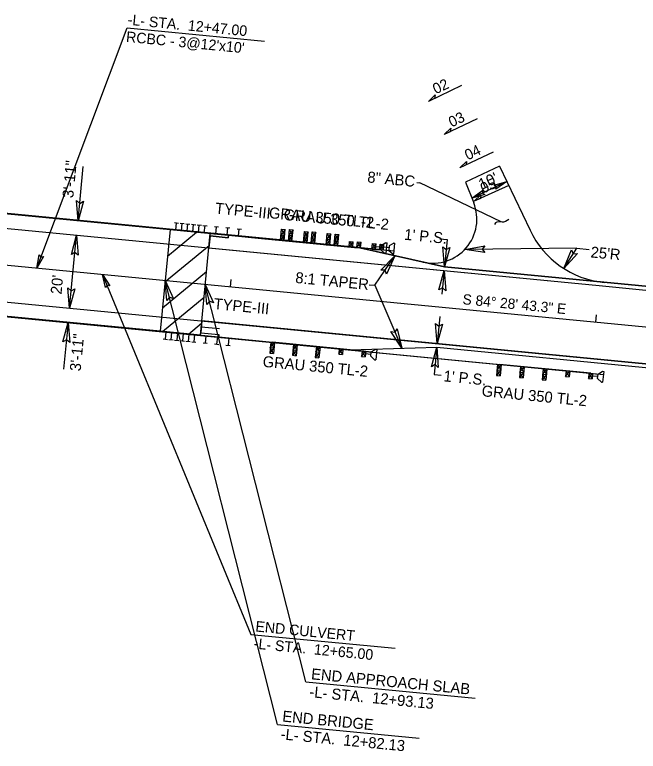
# Model space of a CAD drawing. Extents: x 2061030 to 2061632, y 912568 to 912882.
# Drawn here: x 2061270.2 to 2061440.1, y 912568.1 to 912768.6 of the extents above; entities that cross this region are included whole.
import ezdxf

# ---------------------------------------------------------------- set-up
doc = ezdxf.new("R2010")
doc.units = 0
for name, color, linetype in [('Prop Approach Slab', 7, 'Continuous'), ('Prop Approach Slab Hatching', 7, 'Continuous'), ('Prop Conc Shoulder Berm Gutter', 7, 'Continuous'), ('Prop Dimension', 7, 'Continuous'), ('Prop Dimension Text', 7, 'Continuous'), ('Prop EOT', 7, 'Continuous'), ('Prop Guardrail', 7, 'Continuous'), ('Prop Guardrail Anchor Unit CELL', 7, 'Continuous'), ('Prop Horizontal Alignment', 7, 'Continuous'), ('Prop Horizontal Alignment Direction Label', 7, 'Continuous'), ('Prop Horizontal Alignment Station Label', 7, 'Continuous'), ('Prop Horizontal Alignment Tick Small', 7, 'Continuous'), ('Prop Paved Shoulder', 7, 'Continuous'), ('Prop Roadway Bridge', 7, 'Continuous'), ('Prop Shade Medium', 7, 'Continuous'), ('Prop Structure Anchor Unit CELL', 7, 'Continuous'), ('Prop Terminator CELL', 7, 'Continuous'), ('Scratch_Level_0', 7, 'Continuous')]:
    doc.layers.add(name, color=color, linetype=linetype)

msp = doc.modelspace()

# ---------------------------------------------------------------- linework, layer by layer
at = {"layer": 'Prop Approach Slab'}
for p, q in [((2061323.44, 912709.06), (2061312.49, 912710.12)), ((2061320.76, 912681.36), (2061323.44, 912709.06)), ((2061309.81, 912682.42), (2061320.76, 912681.36))]:
    msp.add_line(p, q, dxfattribs=at)
at = {"layer": 'Prop Approach Slab Hatching'}
for p, q in [((2061311.8, 912702.92), (2061319.7, 912709.43)), ((2061311.11, 912695.88), (2061323.12, 912705.77)), ((2061310.43, 912688.84), (2061322.44, 912698.73)), ((2061310.43, 912682.36), (2061321.76, 912691.69)), ((2061317.47, 912681.68), (2061321.08, 912684.66))]:
    msp.add_line(p, q, dxfattribs=at)
at = {"layer": 'Prop Conc Shoulder Berm Gutter'}
for p, q in [((2061323.44, 912709.06), (2061328.42, 912708.58)), ((2061320.99, 912683.68), (2061325.96, 912683.2)), ((2061320.76, 912681.36), (2061325.74, 912680.88))]:
    msp.add_line(p, q, dxfattribs=at)
at = {"layer": 'Prop Dimension'}
for p, q in [((2061287.41, 912712.55), (2061288.84, 912727.3)), ((2061404.29, 912723.22), (2061394.74, 912718.7)), ((2061379.7, 912722.94), (2061380.52, 912722.86)), ((2061402.72, 912712.22), (2061380.52, 912722.86)), ((2061285.11, 912688.74), (2061287.03, 912708.65)), ((2061385.96, 912707.6), (2061387.99, 912707.4)), ((2061387.99, 912707.4), (2061387.27, 912699.96)), ((2061423.3, 912705.04), (2061392.81, 912704.73)), ((2061419.8, 912699.52), (2061423.3, 912705.04)), ((2061423.3, 912705.04), (2061426.67, 912704.71)), ((2061368.25, 912694.97), (2061373.73, 912703)), ((2061387.17, 912698.97), (2061386.55, 912692.53)), ((2061366.76, 912695.11), (2061368.25, 912694.97)), ((2061368.25, 912694.97), (2061375.66, 912677.8)), ((2061284.73, 912684.84), (2061283.5, 912672.13)), ((2061385.97, 912686.5), (2061385.25, 912679.06)), ((2061385.15, 912678.07), (2061384.43, 912670.63)), ((2061384.43, 912670.63), (2061386.34, 912670.45))]:
    msp.add_line(p, q, dxfattribs=at)
for points in [[(2061398.22, 912703.85), (2061392.81, 912704.73), (2061398.23, 912705.74), (2061397.55, 912704.78)], [(2061423.48, 912703.59), (2061419.8, 912699.52), (2061421.9, 912704.62), (2061422.34, 912703.53)]]:
    msp.add_lwpolyline(points, close=True, dxfattribs=at)
msp.add_open_spline([(2061404.75, 912712.9), (2061403.43, 912711.84), (2061402.8, 912712.5), (2061401.08, 912712.16), (2061400.88, 912711.53)], degree=3, dxfattribs=at)
at = {"layer": 'Prop EOT'}
for p, q in [((2061105.95, 912726.15), (2061429.44, 912694.88)), ((2061104.02, 912706.25), (2061477.28, 912670.17)), ((2061429.44, 912694.88), (2061479.21, 912690.07))]:
    msp.add_line(p, q, dxfattribs=at)
at = {"layer": 'Prop Guardrail'}
for p, q in [((2061343.1, 912707.16), (2061331.15, 912708.32)), ((2061328.48, 912680.62), (2061340.42, 912679.46))]:
    msp.add_line(p, q, dxfattribs=at)
at = {"layer": 'Prop Guardrail Anchor Unit CELL'}
for p, q in [((2061342.6, 912707.21), (2061342.89, 912710.23)), ((2061343.89, 912710.14), (2061342.75, 912708.72)), ((2061343.74, 912708.63), (2061342.89, 912710.23)), ((2061342.89, 912710.23), (2061343.89, 912710.14)), ((2061343.6, 912707.12), (2061343.89, 912710.14)), ((2061348.82, 912706.61), (2061349.11, 912709.63)), ((2061350.11, 912709.54), (2061348.97, 912708.12)), ((2061349.96, 912708.03), (2061349.11, 912709.63)), ((2061349.11, 912709.63), (2061350.11, 912709.54)), ((2061349.82, 912706.52), (2061350.11, 912709.54)), ((2061355.04, 912706.01), (2061355.33, 912709.03)), ((2061356.33, 912708.94), (2061355.19, 912707.52)), ((2061356.19, 912707.43), (2061355.33, 912709.03)), ((2061355.33, 912709.03), (2061356.33, 912708.94)), ((2061356.04, 912705.91), (2061356.33, 912708.94)), ((2061342.6, 912707.21), (2061343.74, 912708.63)), ((2061342.6, 912707.21), (2061343.6, 912707.12)), ((2061342.75, 912708.72), (2061343.74, 912708.63)), ((2061342.75, 912708.72), (2061343.6, 912707.12)), ((2061367.98, 912704.76), (2061343.1, 912707.16)), ((2061348.82, 912706.61), (2061349.96, 912708.03)), ((2061348.97, 912708.12), (2061349.96, 912708.03)), ((2061348.97, 912708.12), (2061349.82, 912706.52)), ((2061355.04, 912706.01), (2061356.19, 912707.43)), ((2061355.19, 912707.52), (2061356.19, 912707.43)), ((2061355.19, 912707.52), (2061356.04, 912705.91)), ((2061361.26, 912705.41), (2061361.41, 912706.92)), ((2061361.41, 912706.92), (2061362.41, 912706.82)), ((2061361.41, 912706.92), (2061362.26, 912705.31)), ((2061348.82, 912706.61), (2061349.82, 912706.52)), ((2061355.04, 912706.01), (2061356.04, 912705.91)), ((2061361.26, 912705.41), (2061362.41, 912706.82)), ((2061361.26, 912705.41), (2061362.26, 912705.31)), ((2061362.26, 912705.31), (2061362.41, 912706.82)), ((2061367.48, 912704.81), (2061367.63, 912706.32)), ((2061367.48, 912704.81), (2061368.63, 912706.22)), ((2061367.63, 912706.32), (2061368.63, 912706.22)), ((2061367.63, 912706.32), (2061368.48, 912704.71)), ((2061368.48, 912704.71), (2061368.63, 912706.22)), ((2061370.01, 912705.3), (2061368.55, 912705.44)), ((2061370.06, 912705.8), (2061369.94, 912704.58)), ((2061371.31, 912706.54), (2061370.06, 912705.8)), ((2061371.31, 912706.54), (2061371.62, 912706.51)), ((2061371.34, 912703.59), (2061371.62, 912706.51)), ((2061367.48, 912704.81), (2061368.48, 912704.71)), ((2061368.48, 912704.72), (2061369.95, 912704.58)), ((2061369.95, 912704.58), (2061371.04, 912703.61)), ((2061371.04, 912703.61), (2061371.34, 912703.59)), ((2061339.92, 912679.51), (2061339.63, 912676.49)), ((2061339.78, 912678), (2061340.92, 912679.41)), ((2061339.92, 912679.51), (2061340.92, 912679.41)), ((2061339.92, 912679.51), (2061340.77, 912677.9)), ((2061365.3, 912677.06), (2061340.42, 912679.46)), ((2061340.92, 912679.41), (2061340.63, 912676.39)), ((2061346.14, 912678.91), (2061345.85, 912675.89)), ((2061346.14, 912678.91), (2061347.14, 912678.81)), ((2061346.14, 912678.91), (2061346.99, 912677.3)), ((2061340.77, 912677.9), (2061339.63, 912676.49)), ((2061339.78, 912678), (2061340.77, 912677.9)), ((2061340.63, 912676.39), (2061339.78, 912678)), ((2061346.99, 912677.3), (2061345.85, 912675.89)), ((2061346, 912677.4), (2061347.14, 912678.81)), ((2061346, 912677.4), (2061346.99, 912677.3)), ((2061346.85, 912675.79), (2061346, 912677.4)), ((2061347.14, 912678.81), (2061346.85, 912675.79)), ((2061352.37, 912678.31), (2061352.07, 912675.28)), ((2061352.22, 912676.79), (2061353.36, 912678.21)), ((2061352.37, 912678.31), (2061353.36, 912678.21)), ((2061352.37, 912678.31), (2061353.21, 912676.7)), ((2061353.36, 912678.21), (2061353.07, 912675.19)), ((2061358.59, 912677.7), (2061358.44, 912676.19)), ((2061358.44, 912676.19), (2061359.58, 912677.61)), ((2061358.59, 912677.7), (2061359.58, 912677.61)), ((2061358.59, 912677.7), (2061359.44, 912676.1)), ((2061359.58, 912677.61), (2061359.44, 912676.1)), ((2061364.81, 912677.1), (2061364.66, 912675.59)), ((2061364.66, 912675.59), (2061365.8, 912677.01)), ((2061364.81, 912677.1), (2061365.8, 912677.01)), ((2061364.81, 912677.1), (2061365.66, 912675.5)), ((2061365.8, 912677.01), (2061365.66, 912675.5)), ((2061365.8, 912677), (2061367.27, 912676.85)), ((2061367.15, 912675.63), (2061367.26, 912676.85)), ((2061367.27, 912676.85), (2061368.52, 912677.59)), ((2061368.52, 912677.59), (2061368.83, 912677.56)), ((2061368.83, 912677.56), (2061368.54, 912674.64)), ((2061339.63, 912676.49), (2061340.63, 912676.39)), ((2061345.85, 912675.89), (2061346.85, 912675.79)), ((2061353.21, 912676.7), (2061352.07, 912675.28)), ((2061352.07, 912675.28), (2061353.07, 912675.19)), ((2061352.22, 912676.79), (2061353.21, 912676.7)), ((2061353.07, 912675.19), (2061352.22, 912676.79)), ((2061358.44, 912676.19), (2061359.44, 912676.1)), ((2061364.66, 912675.59), (2061365.66, 912675.5)), ((2061367.19, 912676.14), (2061365.73, 912676.28)), ((2061368.23, 912674.67), (2061367.15, 912675.63)), ((2061368.23, 912674.67), (2061368.54, 912674.64))]:
    msp.add_line(p, q, dxfattribs=at)
at = {"layer": 'Prop Horizontal Alignment'}
msp.add_line((2061030.33, 912723.42), (2061621.2, 912666.3), dxfattribs=at)
at = {"layer": 'Prop Horizontal Alignment Station Label'}
for p, q in [((2061341.76, 912575.36), (2061311.15, 912696.27)), ((2061349.5, 912586.98), (2061322.1, 912695.21)), ((2061349.5, 912586.98), (2061395.65, 912582.52)), ((2061341.76, 912575.36), (2061380.35, 912571.63))]:
    msp.add_line(p, q, dxfattribs=at)
at = {"layer": 'Prop Horizontal Alignment Tick Small'}
for p, q in [((2061328.94, 912694.55), (2061329.13, 912696.54)), ((2061428.48, 912684.93), (2061428.67, 912686.92))]:
    msp.add_line(p, q, dxfattribs=at)
at = {"layer": 'Prop Paved Shoulder'}
for p, q in [((2061402.29, 912727.44), (2061393.02, 912723.05)), ((2061402.29, 912727.44), (2061410.58, 912709.94)), ((2061393.02, 912723.05), (2061395.26, 912717.37)), ((2061323.44, 912709.06), (2061312.49, 912710.12)), ((2061387.27, 912699.96), (2061479.3, 912691.07)), ((2061320.76, 912681.36), (2061309.81, 912682.42)), ((2061385.15, 912678.07), (2061477.19, 912669.17))]:
    msp.add_line(p, q, dxfattribs=at)
for points in [[(2061323.38, 912708.4), (2061328.35, 912707.92), (2061328.42, 912708.58), (2061337.38, 912707.72), (2061362.76, 912705.26), (2061364.22, 912705.14), (2061387.27, 912699.96)], [(2061320.83, 912682.02), (2061325.8, 912681.54), (2061325.74, 912680.88), (2061334.7, 912680.01), (2061360.08, 912677.56), (2061361.54, 912677.41), (2061385.15, 912678.07)]]:
    msp.add_lwpolyline(points, dxfattribs=at)
for centre, radius, start, end in [((2061384.09, 912712.98), 12, 257.3546, 21.4729), ((2061433.17, 912720.64), 25, 205.3407, 264.4787)]:
    msp.add_arc(centre, radius, start, end, dxfattribs=at)
at = {"layer": 'Prop Roadway Bridge'}
for p, q in [((2061240.58, 912717.07), (2061312.49, 912710.12)), ((2061312.49, 912710.12), (2061309.81, 912682.42)), ((2061309.81, 912682.42), (2061237.9, 912689.37))]:
    msp.add_line(p, q, dxfattribs=at)
at = {"layer": 'Prop Shade Medium'}
for p, q in [((2061323.38, 912708.4), (2061323.06, 912705.17)), ((2061323.06, 912705.17), (2061429.44, 912694.88)), ((2061479.3, 912691.07), (2061387.27, 912699.96)), ((2061429.44, 912694.88), (2061479.21, 912690.07)), ((2061321.14, 912685.26), (2061320.83, 912682.02)), ((2061477.28, 912670.17), (2061321.14, 912685.26)), ((2061385.15, 912678.07), (2061477.19, 912669.17))]:
    msp.add_line(p, q, dxfattribs=at)
for points in [[(2061387.27, 912699.96), (2061364.22, 912705.14), (2061362.76, 912705.26), (2061337.38, 912707.72), (2061328.42, 912708.58), (2061328.35, 912707.92), (2061323.38, 912708.4)], [(2061320.83, 912682.02), (2061325.8, 912681.54), (2061325.74, 912680.88), (2061334.7, 912680.01), (2061360.08, 912677.56), (2061361.54, 912677.41), (2061385.15, 912678.07)]]:
    msp.add_lwpolyline(points, dxfattribs=at)
at = {"layer": 'Prop Structure Anchor Unit CELL'}
for p, q in [((2061313.67, 912712.02), (2061314.81, 912711.91)), ((2061314.05, 912709.97), (2061314.24, 912711.96)), ((2061315.22, 912711.87), (2061316.36, 912711.76)), ((2061315.6, 912709.82), (2061315.79, 912711.81)), ((2061316.78, 912711.72), (2061317.92, 912711.61)), ((2061317.16, 912709.67), (2061317.35, 912711.66)), ((2061318.33, 912711.57), (2061319.47, 912711.46)), ((2061318.71, 912709.52), (2061318.9, 912711.51)), ((2061319.89, 912711.42), (2061321.03, 912711.31)), ((2061320.27, 912709.37), (2061320.46, 912711.36)), ((2061321.45, 912711.27), (2061322.59, 912711.16)), ((2061321.82, 912709.22), (2061322.02, 912711.21)), ((2061324.56, 912710.97), (2061325.7, 912710.86)), ((2061312.49, 912710.12), (2061331.15, 912708.32)), ((2061324.93, 912708.92), (2061325.13, 912710.91)), ((2061327.67, 912710.67), (2061328.81, 912710.56)), ((2061328.04, 912708.62), (2061328.24, 912710.61)), ((2061330.78, 912710.37), (2061331.92, 912710.25)), ((2061331.15, 912708.32), (2061331.35, 912710.31)), ((2061309.81, 912682.42), (2061328.48, 912680.62)), ((2061311.37, 912682.27), (2061311.18, 912680.28)), ((2061312.92, 912682.12), (2061312.73, 912680.13)), ((2061314.48, 912681.97), (2061314.29, 912679.98)), ((2061316.03, 912681.82), (2061315.84, 912679.83)), ((2061317.59, 912681.67), (2061317.4, 912679.68)), ((2061319.14, 912681.52), (2061318.95, 912679.53)), ((2061322.26, 912681.22), (2061322.06, 912679.23)), ((2061325.37, 912680.92), (2061325.17, 912678.93)), ((2061310.61, 912680.33), (2061311.75, 912680.22)), ((2061312.16, 912680.18), (2061313.3, 912680.07)), ((2061313.72, 912680.03), (2061314.86, 912679.92)), ((2061315.27, 912679.88), (2061316.41, 912679.77)), ((2061316.83, 912679.73), (2061317.97, 912679.62)), ((2061318.38, 912679.58), (2061319.52, 912679.47)), ((2061321.49, 912679.28), (2061322.63, 912679.17)), ((2061324.6, 912678.98), (2061325.74, 912678.87)), ((2061328.48, 912680.62), (2061328.28, 912678.62)), ((2061327.71, 912678.68), (2061328.85, 912678.57))]:
    msp.add_line(p, q, dxfattribs=at)
at = {"layer": 'Prop Terminator CELL'}
for points in [[(2061400.77, 912722.24), (2061404.29, 912723.22), (2061401.29, 912721.09), (2061401.44, 912721.87)], [(2061398.25, 912719.68), (2061394.74, 912718.7), (2061397.73, 912720.82), (2061397.59, 912720.05)], [(2061288.86, 912717.83), (2061287.41, 912712.55), (2061286.98, 912718.04), (2061287.87, 912717.27)], [(2061285.59, 912703.36), (2061287.03, 912708.65), (2061287.47, 912703.15), (2061286.58, 912703.93)], [(2061388.72, 912705.25), (2061387.27, 912699.96), (2061386.84, 912705.46), (2061387.73, 912704.68)], [(2061369.92, 912699.07), (2061373.73, 912703), (2061371.46, 912697.98), (2061371.06, 912699.09)], [(2061385.73, 912693.68), (2061387.17, 912698.97), (2061387.61, 912693.47), (2061386.72, 912694.25)], [(2061311.58, 912690.81), (2061311.15, 912696.27), (2061313.42, 912691.24), (2061312.32, 912691.68)], [(2061322.53, 912689.75), (2061322.1, 912695.21), (2061324.36, 912690.18), (2061323.26, 912690.62)], [(2061286.55, 912694.03), (2061285.11, 912688.74), (2061284.68, 912694.24), (2061285.57, 912693.46)], [(2061283.29, 912679.56), (2061284.73, 912684.84), (2061285.17, 912679.35), (2061284.28, 912680.13)], [(2061374.37, 912683.13), (2061375.66, 912677.8), (2061372.63, 912682.41), (2061373.78, 912682.15)], [(2061386.69, 912684.35), (2061385.25, 912679.06), (2061384.81, 912684.56), (2061385.7, 912683.78)], [(2061383.71, 912672.78), (2061385.15, 912678.07), (2061385.58, 912672.57), (2061384.7, 912673.35)]]:
    msp.add_lwpolyline(points, close=True, dxfattribs=at)
at = {"layer": 'Scratch_Level_0'}
for p, q in [((2061276.19, 912699.65), (2061300.77, 912765.03)), ((2061300.77, 912765.03), (2061338.21, 912761.41)), ((2061391.93, 912749.32), (2061382.9, 912745.04)), ((2061396.21, 912740.28), (2061387.18, 912736)), ((2061400.49, 912731.24), (2061391.46, 912726.96)), ((2061181.53, 912722.87), (2061373.54, 912704.31)), ((2061404.81, 912722.11), (2061395.34, 912717.85)), ((2061345.22, 912707.04), (2061209.85, 912720.13)), ((2061344.72, 912707.09), (2061345.01, 912710.11)), ((2061346.01, 912710.02), (2061344.87, 912708.6)), ((2061345.86, 912708.51), (2061345.01, 912710.11)), ((2061345.01, 912710.11), (2061346.01, 912710.02)), ((2061345.71, 912707), (2061346.01, 912710.02)), ((2061350.94, 912706.49), (2061351.23, 912709.51)), ((2061352.23, 912709.42), (2061351.09, 912708)), ((2061352.08, 912707.91), (2061351.23, 912709.51)), ((2061351.23, 912709.51), (2061352.23, 912709.42)), ((2061351.94, 912706.39), (2061352.23, 912709.42)), ((2061344.72, 912707.09), (2061345.86, 912708.51)), ((2061344.72, 912707.09), (2061345.71, 912707)), ((2061344.87, 912708.6), (2061345.86, 912708.51)), ((2061344.87, 912708.6), (2061345.71, 912707)), ((2061370.1, 912704.64), (2061345.22, 912707.04)), ((2061350.94, 912706.49), (2061352.08, 912707.91)), ((2061351.09, 912708), (2061352.08, 912707.91)), ((2061351.09, 912708), (2061351.94, 912706.39)), ((2061357.16, 912705.89), (2061357.45, 912708.91)), ((2061357.16, 912705.89), (2061358.3, 912707.3)), ((2061358.45, 912708.81), (2061357.31, 912707.4)), ((2061357.31, 912707.4), (2061358.3, 912707.3)), ((2061357.31, 912707.4), (2061358.16, 912705.79)), ((2061358.3, 912707.3), (2061357.45, 912708.91)), ((2061357.45, 912708.91), (2061358.45, 912708.81)), ((2061358.16, 912705.79), (2061358.45, 912708.81)), ((2061350.94, 912706.49), (2061351.94, 912706.39)), ((2061357.16, 912705.89), (2061358.16, 912705.79)), ((2061363.38, 912705.29), (2061363.53, 912706.8)), ((2061363.38, 912705.29), (2061364.52, 912706.7)), ((2061363.38, 912705.29), (2061364.38, 912705.19)), ((2061363.53, 912706.8), (2061364.52, 912706.7)), ((2061363.53, 912706.8), (2061364.38, 912705.19)), ((2061364.38, 912705.19), (2061364.52, 912706.7)), ((2061369.6, 912704.69), (2061369.75, 912706.2)), ((2061369.6, 912704.69), (2061370.75, 912706.1)), ((2061369.75, 912706.2), (2061370.74, 912706.1)), ((2061369.75, 912706.2), (2061370.6, 912704.59)), ((2061370.6, 912704.59), (2061370.74, 912706.1)), ((2061372.13, 912705.18), (2061370.67, 912705.32)), ((2061372.18, 912705.68), (2061372.06, 912704.46)), ((2061373.43, 912706.42), (2061372.18, 912705.68)), ((2061373.43, 912706.42), (2061373.74, 912706.39)), ((2061373.46, 912703.46), (2061373.74, 912706.39)), ((2061369.6, 912704.69), (2061370.6, 912704.59)), ((2061370.6, 912704.6), (2061372.06, 912704.46)), ((2061372.06, 912704.46), (2061373.15, 912703.49)), ((2061373.15, 912703.49), (2061373.46, 912703.46)), ((2061294.1, 912697.92), (2061334.49, 912599.9)), ((2061178.83, 912695), (2061430.57, 912670.66)), ((2061207.15, 912692.26), (2061402.24, 912673.4)), ((2061401.75, 912673.45), (2061401.45, 912670.43)), ((2061401.6, 912671.94), (2061402.74, 912673.35)), ((2061401.75, 912673.45), (2061402.74, 912673.35)), ((2061401.75, 912673.45), (2061402.6, 912671.84)), ((2061427.13, 912671), (2061402.24, 912673.4)), ((2061402.74, 912673.35), (2061402.45, 912670.33)), ((2061407.97, 912672.85), (2061407.68, 912669.83)), ((2061407.97, 912672.85), (2061408.96, 912672.75)), ((2061407.97, 912672.85), (2061408.82, 912671.24)), ((2061402.6, 912671.84), (2061401.45, 912670.43)), ((2061401.6, 912671.94), (2061402.6, 912671.84)), ((2061402.45, 912670.33), (2061401.6, 912671.94)), ((2061408.82, 912671.24), (2061407.68, 912669.83)), ((2061407.82, 912671.34), (2061408.96, 912672.75)), ((2061407.82, 912671.34), (2061408.82, 912671.24)), ((2061408.67, 912669.73), (2061407.82, 912671.34)), ((2061408.96, 912672.75), (2061408.67, 912669.73)), ((2061414.19, 912672.25), (2061413.9, 912669.22)), ((2061414.04, 912670.73), (2061415.18, 912672.15)), ((2061414.19, 912672.25), (2061415.18, 912672.15)), ((2061414.19, 912672.25), (2061415.04, 912670.64)), ((2061415.18, 912672.15), (2061414.89, 912669.13)), ((2061420.41, 912671.64), (2061420.26, 912670.13)), ((2061420.26, 912670.13), (2061421.41, 912671.55)), ((2061420.41, 912671.64), (2061421.41, 912671.55)), ((2061420.41, 912671.64), (2061421.26, 912670.04)), ((2061421.41, 912671.55), (2061421.26, 912670.04)), ((2061426.63, 912671.04), (2061426.48, 912669.53)), ((2061426.49, 912669.53), (2061427.63, 912670.95)), ((2061426.63, 912671.04), (2061427.63, 912670.95)), ((2061426.63, 912671.04), (2061427.48, 912669.44)), ((2061427.63, 912670.95), (2061427.48, 912669.44)), ((2061427.63, 912670.94), (2061429.09, 912670.79)), ((2061429.09, 912670.79), (2061430.34, 912671.53)), ((2061430.34, 912671.53), (2061430.65, 912671.5)), ((2061430.65, 912671.5), (2061430.36, 912668.58)), ((2061401.45, 912670.43), (2061402.45, 912670.33)), ((2061407.68, 912669.83), (2061408.67, 912669.73)), ((2061415.04, 912670.64), (2061413.9, 912669.22)), ((2061413.9, 912669.22), (2061414.89, 912669.13)), ((2061414.04, 912670.73), (2061415.04, 912670.64)), ((2061414.89, 912669.13), (2061414.04, 912670.73)), ((2061420.26, 912670.13), (2061421.26, 912670.04)), ((2061426.48, 912669.53), (2061427.48, 912669.44)), ((2061429.02, 912670.08), (2061427.56, 912670.22)), ((2061428.97, 912669.57), (2061429.09, 912670.79)), ((2061430.06, 912668.61), (2061428.97, 912669.57)), ((2061430.06, 912668.61), (2061430.36, 912668.58)), ((2061334.49, 912599.9), (2061373.81, 912596.1))]:
    msp.add_line(p, q, dxfattribs=at)
for points in [[(2061382.9, 912745.04), (2061384.72, 912746.79), (2061384.57, 912745.83)], [(2061387.18, 912736), (2061389, 912737.75), (2061388.85, 912736.79)], [(2061391.46, 912726.96), (2061393.28, 912728.71), (2061393.13, 912727.75)], [(2061395.34, 912717.85), (2061397.2, 912719.57), (2061397.03, 912718.61)], [(2061278.03, 912702.8), (2061276.19, 912699.65), (2061276.86, 912703.26), (2061277.3, 912702.61)], [(2061294.9, 912694.35), (2061294.1, 912697.92), (2061296.07, 912694.82), (2061295.31, 912695)]]:
    msp.add_lwpolyline(points, close=True, dxfattribs=at)

# ---------------------------------------------------------------- texts
at = {"layer": 'Prop Dimension'}
msp.add_text("25'R", height=3, rotation=354.4787, dxfattribs=at).set_placement((2061426.98, 912702.56))
at = {"layer": 'Prop Dimension Text'}
for s, rotation, p in [('3\'-11"', 84.4787, (2061286.11, 912718.62)), ('8" ABC', 354.4787, (2061366.13, 912722.99)), ("10'", 25.3407, (2061397.42, 912720.9)), ("1' P.S.", 354.4787, (2061376.17, 912707.37)), ("20'", 84.4787, (2061282.9, 912692.4)), ('8:1 TAPER', 354.4787, (2061346.52, 912695.61)), ('3\'-11"', 84.4787, (2061288.12, 912671.45)), ("1' P.S.", 354.4787, (2061386.9, 912668.81))]:
    msp.add_text(s, height=3, rotation=rotation, dxfattribs=at).set_placement(p)
at = {"layer": 'Prop Guardrail Anchor Unit CELL'}
for p in [(2061343.33, 912712.78), (2061337.63, 912672.77)]:
    msp.add_text('GRAU 350 TL-2', height=3, rotation=354.4787, dxfattribs=at).set_placement(p)
at = {"layer": 'Prop Horizontal Alignment Direction Label'}
msp.add_text('S 84%%d 28\' 43.3" E', height=2.8, rotation=354.4787, dxfattribs=at).set_placement((2061392.09, 912689.82))
at = {"layer": 'Prop Horizontal Alignment Station Label'}
for s, p in [('END APPROACH SLAB', (2061350.83, 912587.67)), ('-L- STA.  12+93.13', (2061350.36, 912582.82)), ('END BRIDGE', (2061342.98, 912576.16)), ('-L- STA.  12+82.13', (2061342.51, 912571.31))]:
    msp.add_text(s, height=3, rotation=354.4787, dxfattribs=at).set_placement(p)
at = {"layer": 'Prop Structure Anchor Unit CELL'}
for p in [(2061324.66, 912714.51), (2061324.27, 912688.49)]:
    msp.add_text('TYPE-III', height=3, rotation=354.4787, dxfattribs=at).set_placement(p)
at = {"layer": 'Scratch_Level_0'}
for s, height, rotation, p in [('-L- STA.  12+47.00', 2.88, 354.4787, (2061300.86, 912765.92)), ("RCBC - 3@12'x10'", 2.88, 354.4787, (2061300.41, 912761.26)), ('02', 2.88, 25.3407, (2061384.89, 912746.94)), ('03', 2.88, 25.3407, (2061389.21, 912737.92)), ('04', 2.88, 25.3407, (2061393.61, 912728.94)), ('05', 2.88, 24.2122, (2061397.83, 912719.92)), ('GRAU 350 TL-2', 3, 354.4787, (2061339.32, 912713.27)), ('GRAU 350 TL-2', 3, 354.4787, (2061397.29, 912664.77)), ('END CULVERT', 2.88, 354.4787, (2061335.65, 912600.69)), ('-L- STA.  12+65.00', 2.88, 354.4787, (2061335.2, 912596.03))]:
    msp.add_text(s, height=height, rotation=rotation, dxfattribs=at).set_placement(p)

doc.saveas('drawing.dxf')
